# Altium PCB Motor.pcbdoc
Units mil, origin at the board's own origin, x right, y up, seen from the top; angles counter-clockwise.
Board outline 2316 x 2435.6 mil, 4 copper layers (Top Layer, SIG, GND, Bottom Layer), stack 62.5 mil thick; 70 components, 50 nets, 223 pads, 137 vias.
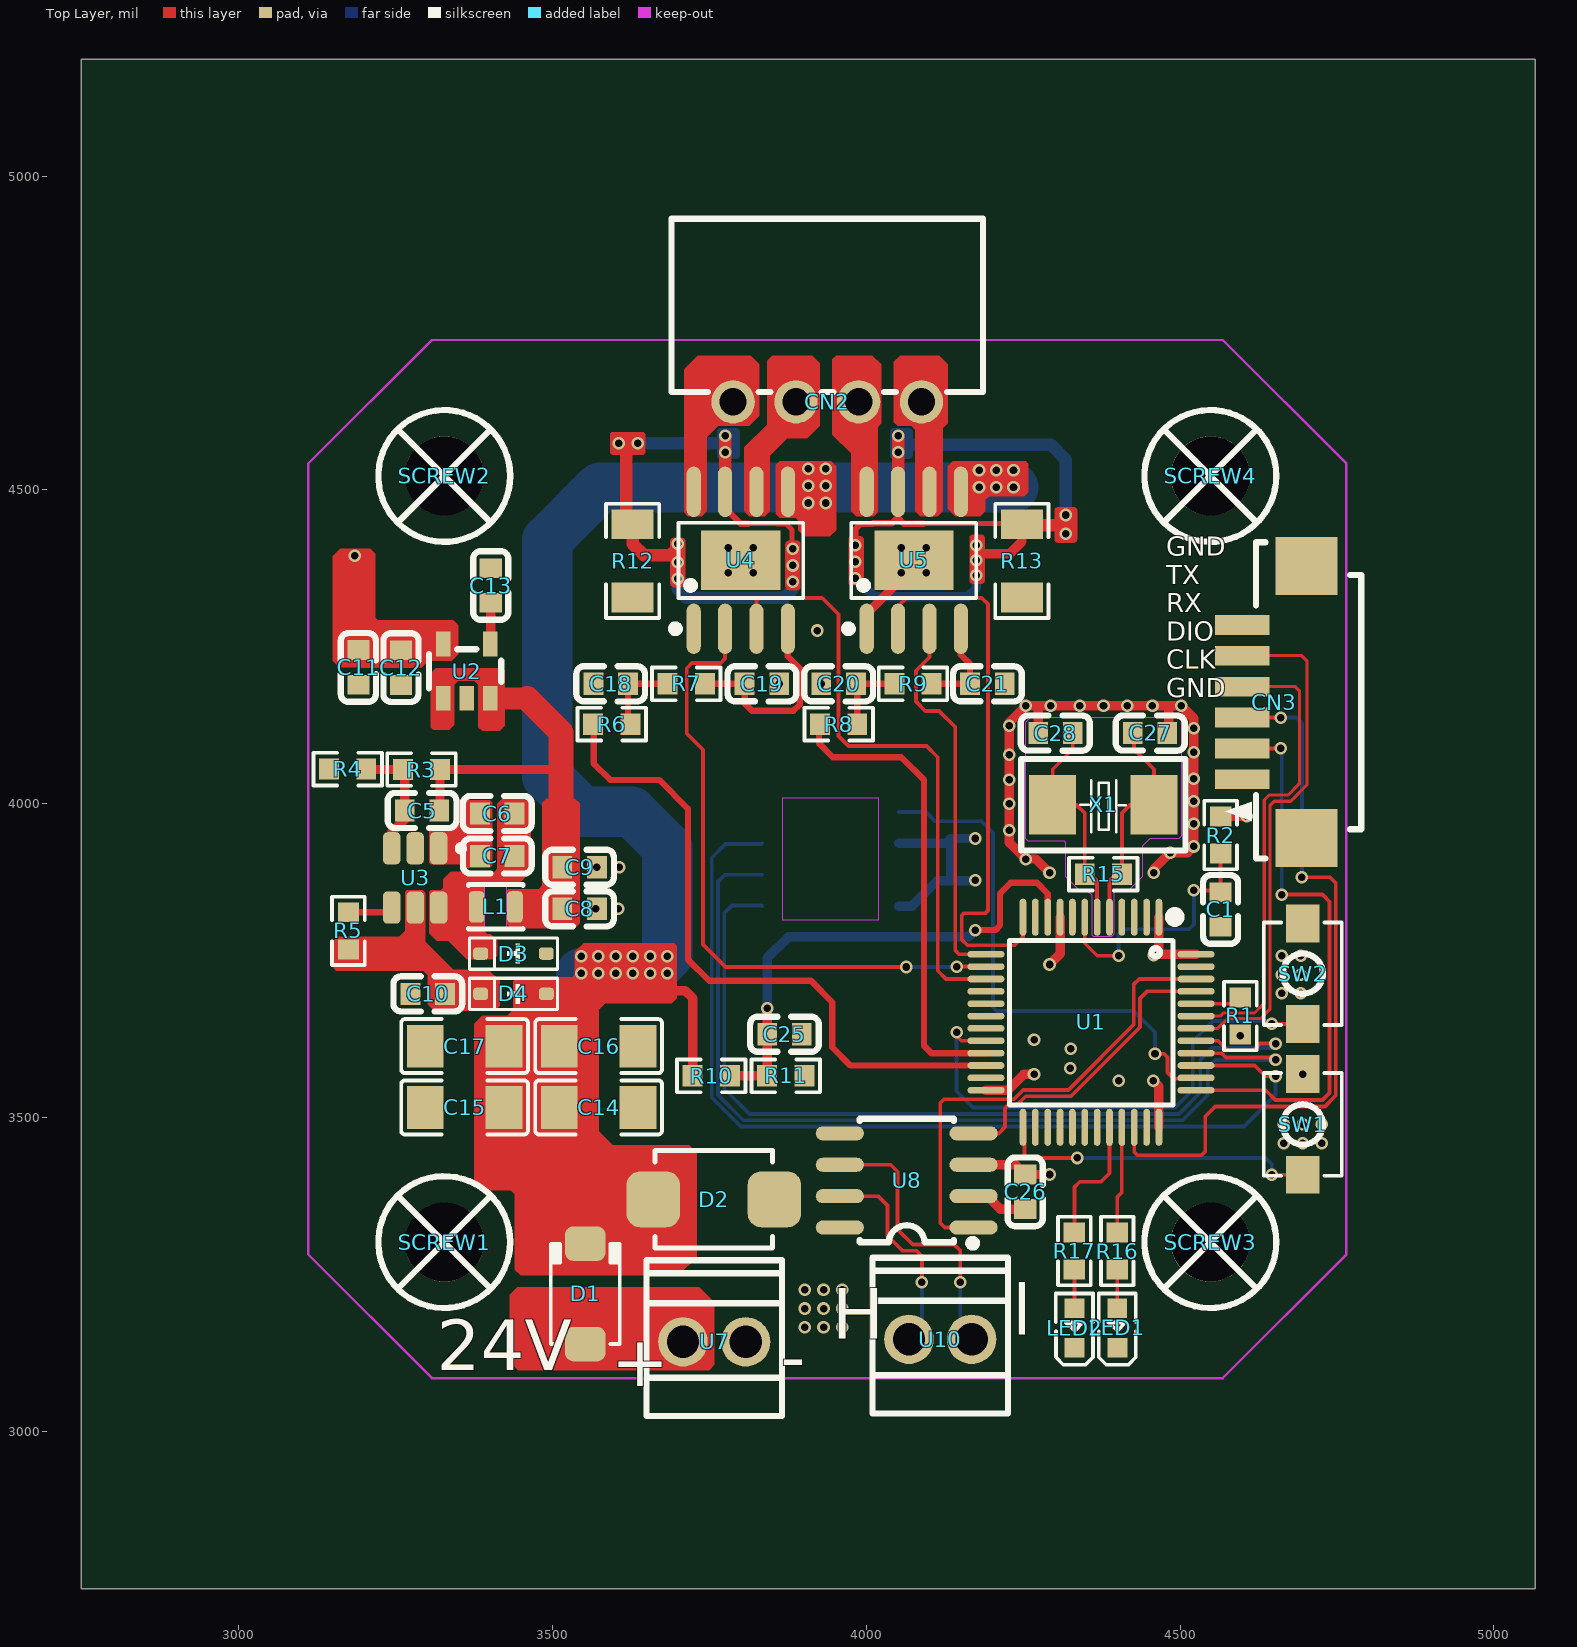
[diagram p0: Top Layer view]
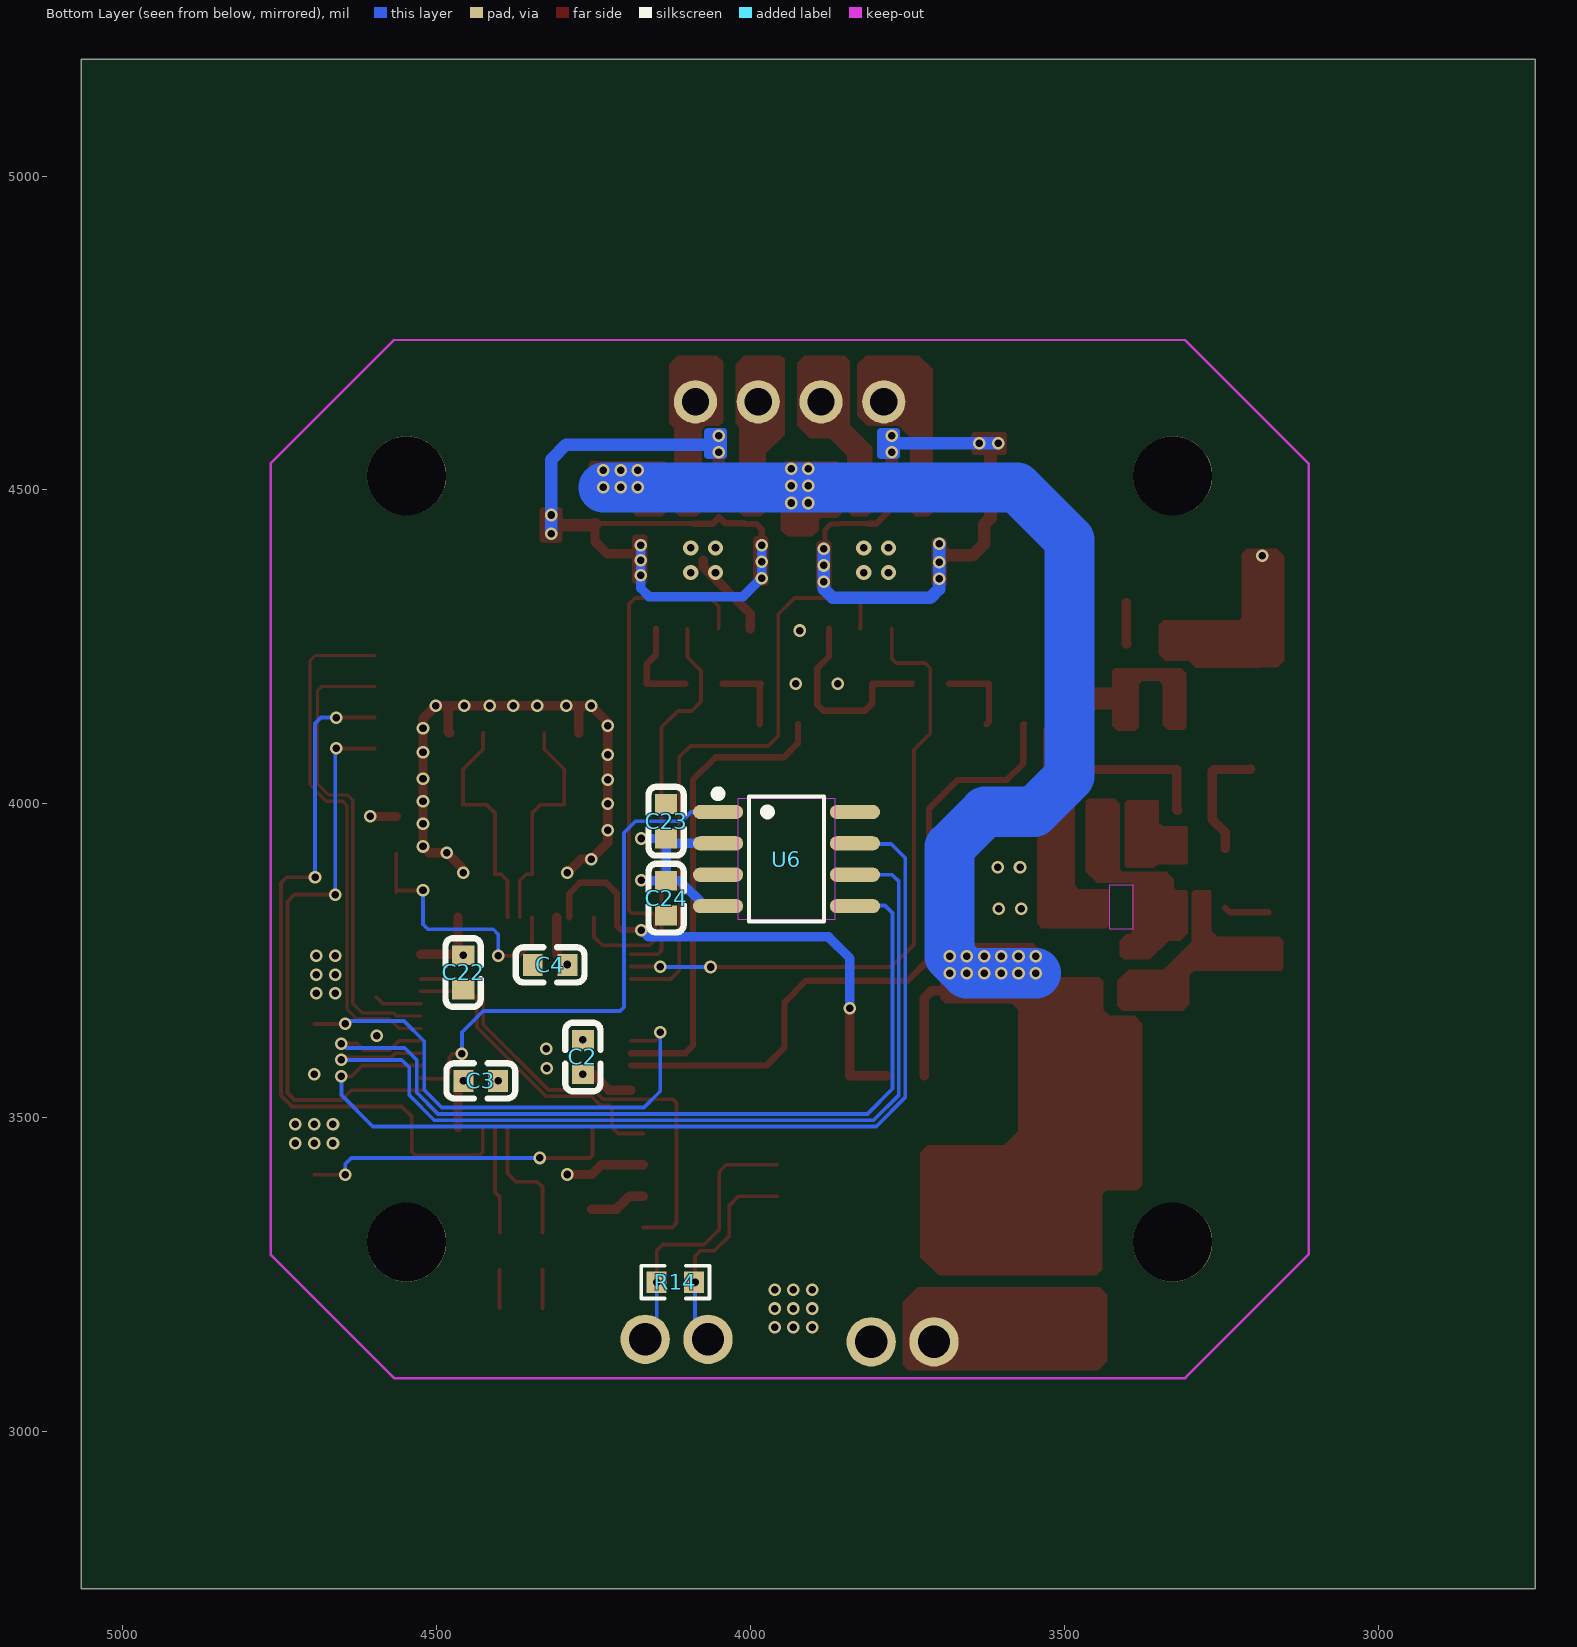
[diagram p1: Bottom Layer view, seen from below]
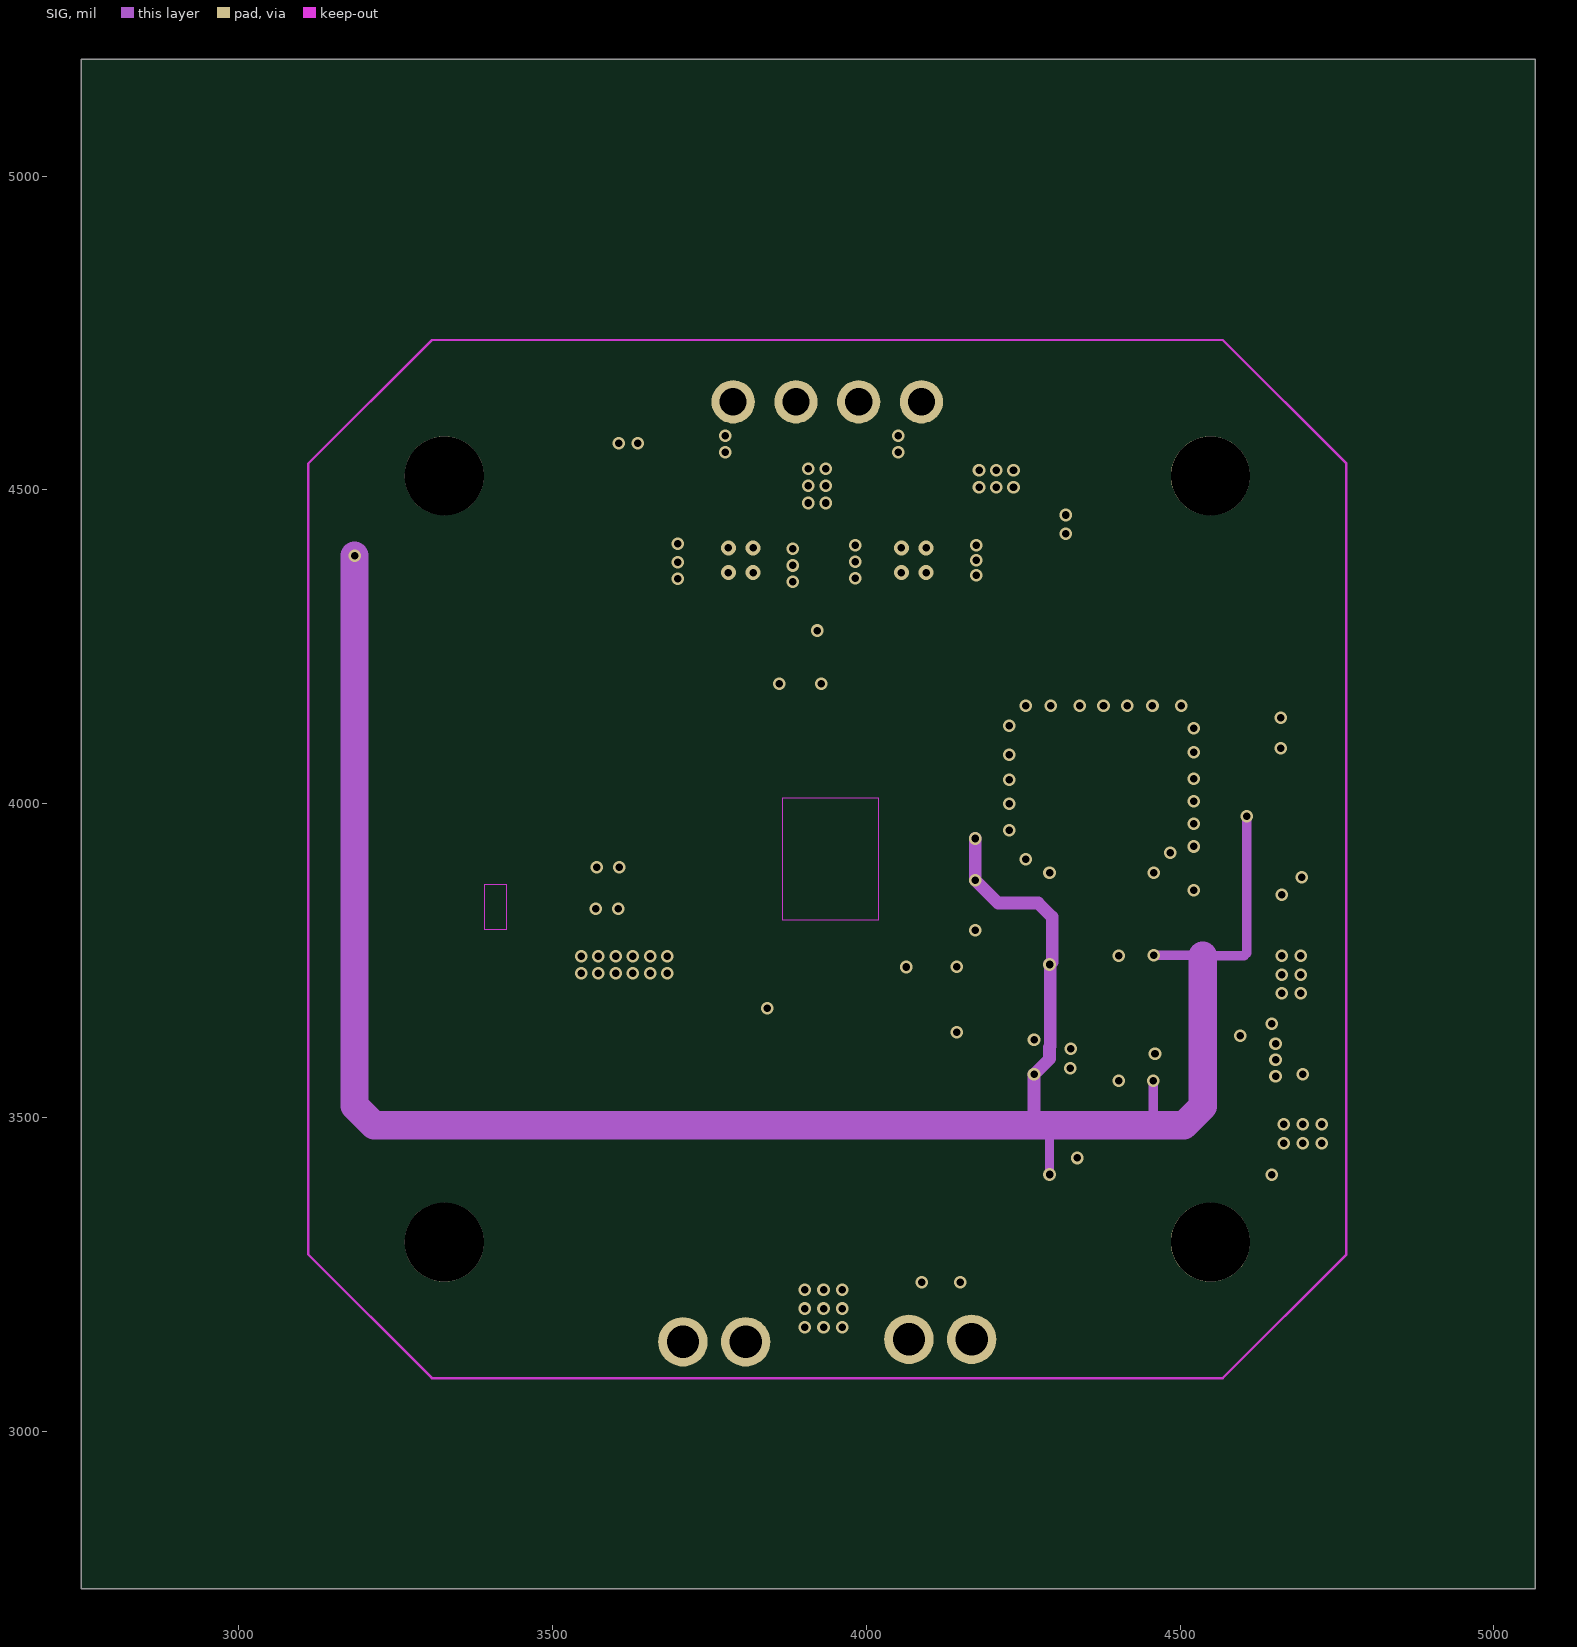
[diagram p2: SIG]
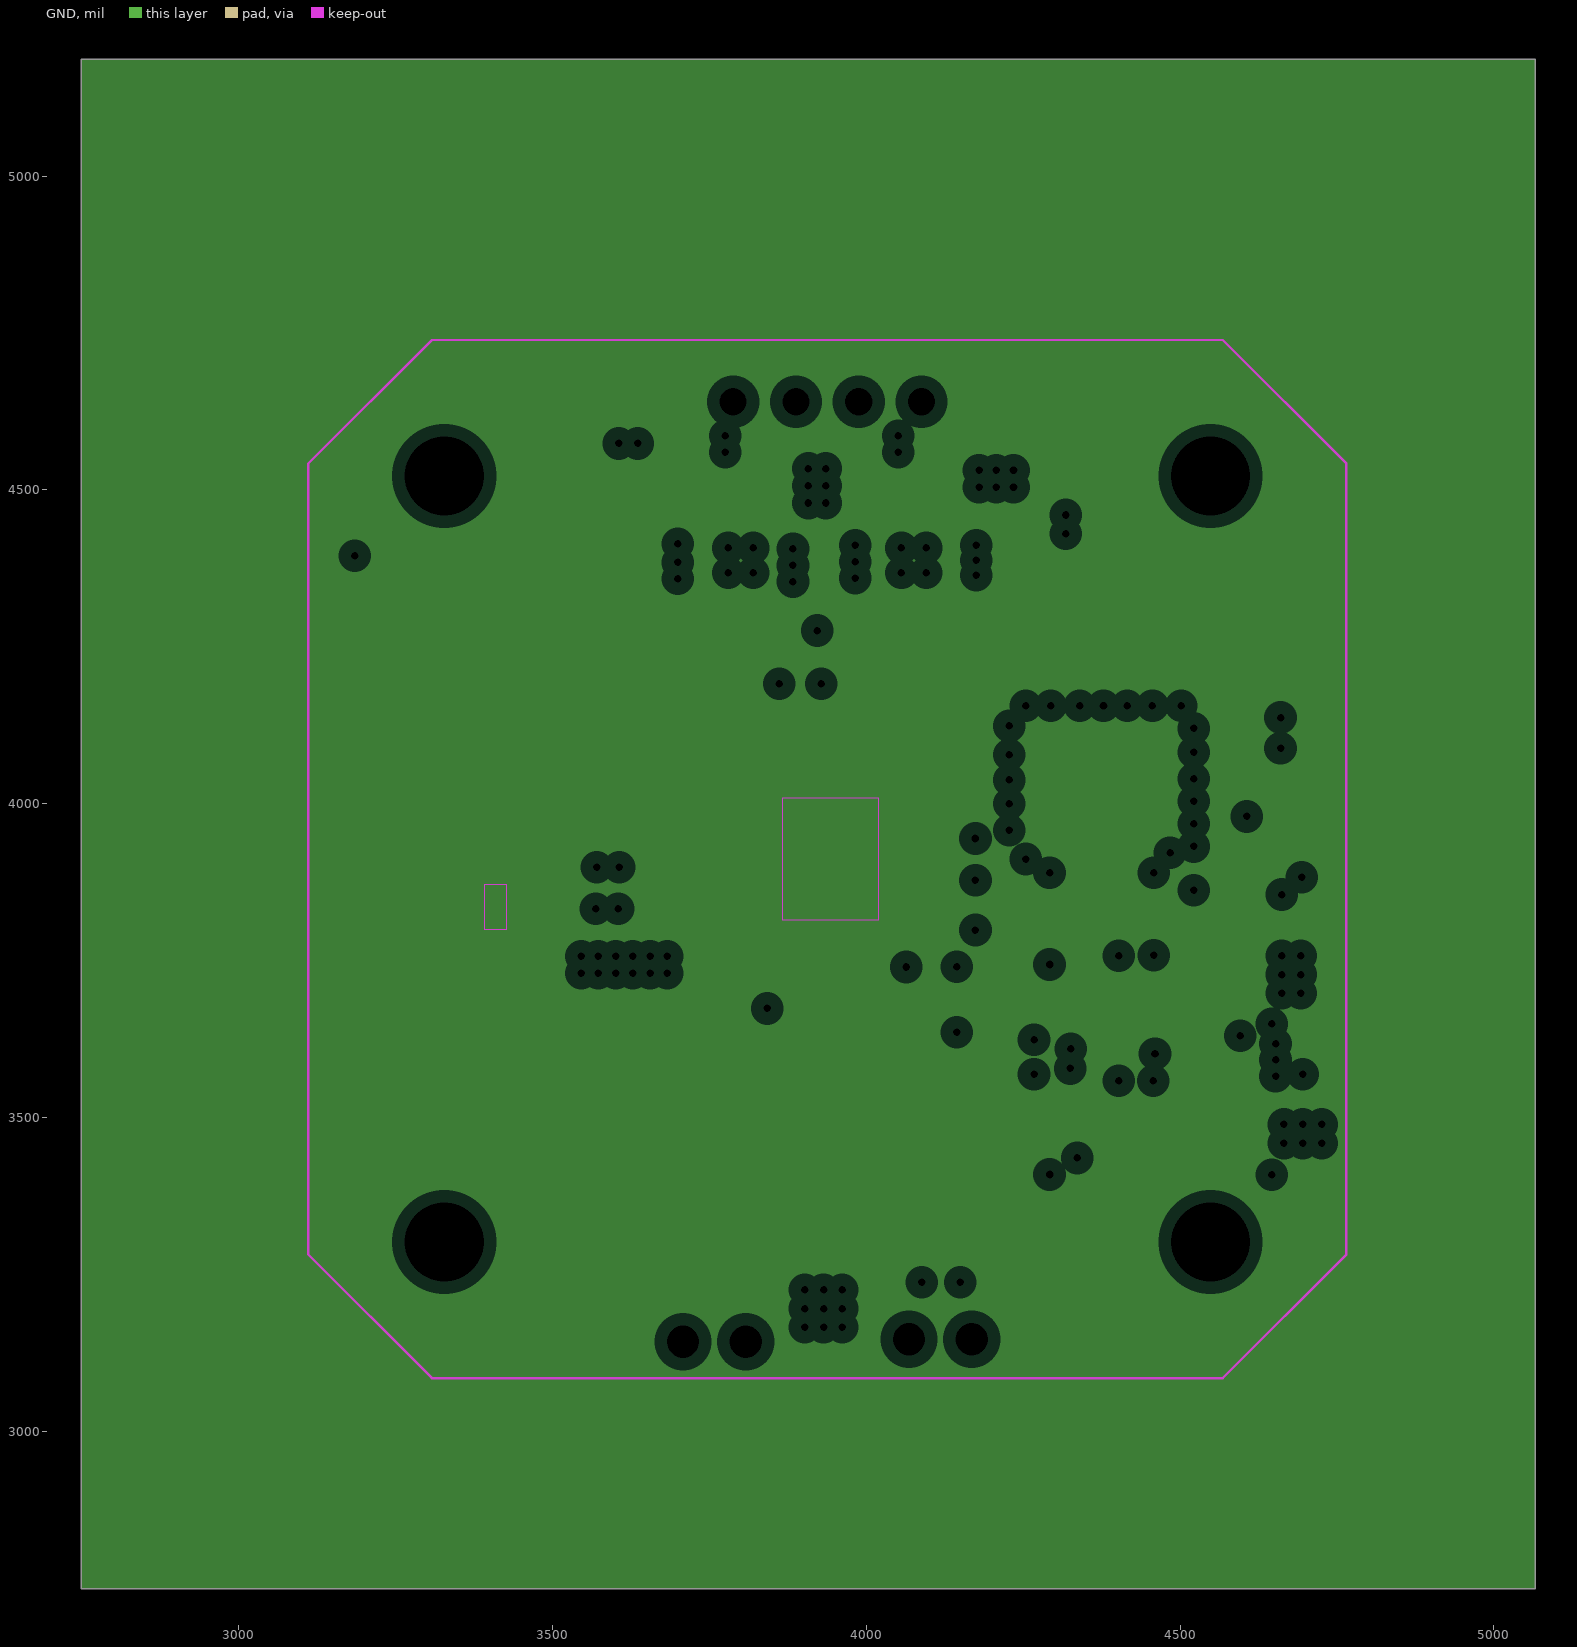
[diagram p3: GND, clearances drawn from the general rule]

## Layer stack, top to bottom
Top Layer: signal copper 1.4
Dielectric1: surface 8.3, 7628 RC49% 8.6mil, Dk 0
SIG: signal copper 0.6
Dielectric2: surface 41.9, 1.1mm H/HOZ Copper, Dk 0
GND: plane copper 0.6
Dielectric3: surface 8.3, 7628 RC49% 8.6mil, Dk 0
Bottom Layer: signal copper 1.4

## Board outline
5066,2750 2750,2750 2750,5185.6 5066,5185.6

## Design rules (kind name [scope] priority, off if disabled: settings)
BoardOutlineClearance copperThickness1oz [All] p0: genericclearance=10 ignorepadtopadclearanceinfootprint=FALSE except(0: Arc-SplitContinuation Track-SplitContinuation SMDPad-SplitContinuation THPad-SplitContinuation Via-SplitContinuation Fill-SplitContinuation Poly-SplitContinuation Region-SplitContinuation Text-SplitContinuation)
BoardOutlineClearance copperThickness2oz [All] p0: genericclearance=10 ignorepadtopadclearanceinfootprint=FALSE except(0: Arc-SplitContinuation Track-SplitContinuation SMDPad-SplitContinuation THPad-SplitContinuation Via-SplitContinuation Fill-SplitContinuation Poly-SplitContinuation Region-SplitContinuation Text-SplitContinuation)
BoardOutlineClearance otherClearance [All] p0: genericclearance=10 ignorepadtopadclearanceinfootprint=FALSE except(0: Arc-SplitContinuation Track-SplitContinuation SMDPad-SplitContinuation THPad-SplitContinuation Via-SplitContinuation Fill-SplitContinuation Poly-SplitContinuation Region-SplitContinuation Text-SplitContinuation)
Clearance copperThickness1oz [All] p1: gap=7 ignorepadtopadclearanceinfootprint=FALSE
Clearance copperThickness2oz [All] p1: gap=7 ignorepadtopadclearanceinfootprint=FALSE
Clearance otherClearance [All] p1: gap=7 ignorepadtopadclearanceinfootprint=FALSE
DiffPairsRouting differentialPair [All] p1: maxuncoupledlength=10 minlimit=6 maxlimit=Infinity mostfreqgap=6 toplayer_minwidth=5 toplayer_prefwidth=10 toplayer_maxwidth=100 bottomlayer_minwidth=5 bottomlayer_prefwidth=10 bottomlayer_maxwidth=100 midlayer1_minwidth=5 midlayer1_prefwidth=10 midlayer1_maxwidth=100
PasteMaskExpansion pasteMaskExpansion [All] p1: expansion=0
PlaneConnect innerPlane [All] p1: planeconnectstyle=Relief reliefexpansion=20 reliefentries=4 reliefconductorwidth=10 reliefairgap=10
PolygonConnect copperRegion [All] p1: connectstyle=Direct reliefentries=4 reliefconductorwidth=10 polygonreliefangle="90 Angle" airgapwidth=10
RoutingVias viaSize [All] p1: viastyle="Through Hole" holewidth=12.0078 minholewidth=12 maxholewidth=12.0078 width=12.0078 minwidth=12 maxwidth=12.0078
SolderMaskExpansion solderMaskExpansion [IsVia] p1: useseparateexpansions=TRUE expansion=-1000 expansionbottom=-1000
SolderMaskExpansion solderMaskExpansion [All] p2: useseparateexpansions=TRUE expansion=2 expansionbottom=2
Width copperThickness1oz [All] p1: maxlimit=100 minlimit=5 preferedwidth=6
Width copperThickness2oz [All] p1: maxlimit=100 minlimit=8 preferedwidth=10
Width PWR [All] p1: maxlimit=100 minlimit=10 preferedwidth=15

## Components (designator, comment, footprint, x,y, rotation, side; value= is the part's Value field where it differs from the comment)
C1 "100nF" C0603_2#1 4564.5,3831.7 r90 top
C2 "100nF" C0603_2#2 4267.3,3596.7 r270 bottom
C3 "100nF" C0603_2#3 4429.9,3558.6 r0 bottom
C4 "100nF" C0603_2#2 4319.5,3743.3 r180 bottom
C5 "100nF" C0603_2#3 3292.4,3989.3 r0 top
C6 "100nF" C0603_2#1 3412.4,3984.5 r0 top
C7 "100nF" C0603_2#1 3412.4,3916.9 r0 top
C8 "100nF" C0603_2#1 3543.4,3832.7 r180 top
C9 "100nF" C0603_2#1 3543.4,3898.9 r180 top
C10 "100nF" C0603_2#2 3301.6,3697.2 r0 top
C11 "100nF" C0603_2#2 3191.1,4217.2 r90 top
C12 "100nF" C0603_2#1 3258.9,4217 r90 top
C13 "100nF" C0603_2#2 3401.9,4347.7 r270 top
C14 "LMK316B7226ML-TR" C1206 3573.8,3516.3 r180 top
C15 "LMK316B7226ML-TR" C1206 3360.2,3516.3 r0 top
C16 "LMK316B7226ML-TR" C1206 3573.8,3614 r180 top
C17 "LMK316B7226ML-TR" C1206 3360.2,3614 r0 top
C18 "100nF" C0603_2#3 3592.9,4191.1 r0 top
C19 "100nF" C0603_2#3 3833.9,4191.1 r180 top
C20 "100nF" C0603_2#1 3956.1,4191.1 r0 top
C21 "100nF" C0603_2#2 4193,4191.1 r180 top
C22 "100nF" C0603_2#2 4458,3731.3 r90 bottom
C23 "100nF" C0603_2#1 4134.8,3972.2 r270 bottom
C24 "100nF" C0603_2#1 4134.8,3849.8 r90 bottom
C25 "100nF" C0603_2#1 3869.7,3632.9 r180 top
C26 "100nF" C0603_2#3 4253.2,3381.9 r90 top
C27 "22pF" C0603_1#1 4452,4112.8 r180 top
C28 "22pF" C0603_1#2 4301.4,4112.6 r0 top
CN2 "XH-4AW" CONN-TH_XH-4AW 3938,4640.3 r180 top
CN3 "1.25-6PWT" CONN-SMD_1.25-6PWT-C2763634 4650,4162 r90 top
D1 "=value" DO-214AC 3552.5,3219.3 r90 top
D2 "SMBJ28CA" SMBJ-CA_MFG 3757.3,3369.9 r0 top
D3 "二极管-5819W" SOD-323 3438,3761.4 r180 top
D4 "二极管-5819W" SOD-323 3438.1,3697.2 r180 top
L1 "6.8uH" IND-201612 3409.9,3835.7 r0 top
LED1 "" LED_0603 4399.8,3167.1 r90 top
LED2 "" LED_0603 4331.6,3167.1 r90 top
R1 "10K" R0603_2#1 4596,3662 r270 top
R2 "10K" R0603_2#2 4564.5,3950.1 r90 top
R3 "10K" R0603_2#3 3291.5,4054.6 r0 top
R4 "10K" R0603_2#3 3174,4055.3 r0 top
R5 "10K" R0603_2#3 3175.2,3797.6 r90 top
R6 "10K" R0603_2#2 3594.7,4126.8 r0 top
R7 "10K" R0603_2#1 3713.4,4191.1 r0 top
R8 "10K" R0603_2#3 3956.1,4126.8 r0 top
R9 "10K" R0603_2#2 4074.5,4191.1 r0 top
R10 "10K" R0603_2#2 3753.3,3566.6 r180 top
R11 "10K" R0603_2#3 3871.7,3566.6 r180 top
R12 "10K" R1206 3628,4387 r270 top
R13 "10K" R1206 4248,4387 r270 top
R14 "10K" R0603_2#1 4120,3238 r180 bottom
R15 "10K" R0603_1 4377.7,3887.9 r180 top
R16 "10K" R0603_2#3 4399.8,3287.6 r90 top
R17 "10K" R0603_2#3 4331.6,3287.6 r90 top
SCREW1 "" M3螺丝 3327.8,3301.8 r0 top locked
SCREW2 "" M3螺丝 3327.8,4522.2 r0 top locked
SCREW3 "" M3螺丝 4548.2,3301.8 r0 top locked
SCREW4 "" M3螺丝 4548.2,4522.2 r0 top locked
SW1 "" Key_SMD_3x4x2_1#1 4695.4,3489.2 r90 top
SW2 "" Key_SMD_3x4x2_1#2 4695.4,3729.4 r90 top
U1 "STM32F103CBT6" LQFP-48_L7.0-W7.0-P0.50-LS9.0-BL 4358,3652 r180 top
U2 "LP2992IM5-3.3" SOT-23-5_L2.9-W1.6-P0.95-LS2.8-BL 3363.7,4211.2 r0 top
U3 "ME3116" SOT23-6 3281.6,3881.9 r270 top
U4 "TB67H450FNG,EL" HSOP-8_L5.0-W4.0-P1.27-LS6.2-BL-EP 3800.2,4387.9 r0 top
U5 "TB67H450FNG,EL" HSOP-8_L5.0-W4.0-P1.27-LS6.2-BL-EP 4075.8,4387.9 r0 top
U6 "MT6816CT-ACD" SOP-8_L5.0-W4.0-P1.27-LS6.0-BL 3943,3912 r270 bottom
U7 "KF128-2.54-2P" CONN-TH_P2.54_KF128-2.54-2P 3758,3143 r180 top
U8 "SN65HVD232DR" SOIC-8_L5.0-W4.0-P1.27-LS6.0-BL 4064.5,3400 r90 top
U10 "KF128-2.54-2P" CONN-TH_P2.54_KF128-2.54-2P 4118,3147 r180 top
X1 "12MHz" OSC-SMD_L5.0-W3.2 4377.7,3998.3 r0 top

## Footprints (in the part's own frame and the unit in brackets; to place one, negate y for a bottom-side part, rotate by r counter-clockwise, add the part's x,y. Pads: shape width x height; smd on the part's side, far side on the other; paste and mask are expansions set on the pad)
C0603_1#1 [mil]
  rect 31.5x35.4 smd paste+0 mask+2: 1(-27.6,0) 2(27.5,0)
  silkscreen extent -55,-28 55,28
C0603_1#2 [mil]
  rect 31.5x35.4 smd paste+0 mask+2: 1(-27.5,0) 2(27.6,0)
  silkscreen extent -55,-28 55,28
C0603_2#1 [mil]
  rect 31.5x35.4 smd: 1(-27.6,0) 2(27.5,0)
  silkscreen extent -55,-28 55,28
C0603_2#2 [mil]
  rect 31.5x35.4 smd: 1(-27.6,0) 2(27.6,0)
  silkscreen extent -55,-28 55,28
C0603_2#3 [mil]
  rect 31.5x35.4 smd: 1(-27.5,0) 2(27.6,0)
  silkscreen extent -55,-28 55,28
C1206 [mil]
  rect 58.5x68 smd paste-3937 mask+2: 1(-62.7,0) 2(62.7,0)
  silkscreen extent -101,-43 101,43
CONN-SMD_1.25-6PWT-C2763634 [mil]
  rect 31.5x86.6 smd paste+0 mask+2: 1(-123,51.2) 2(-73.8,51.2) 3(-24.6,51.2) 4(24.6,51.2) 5(73.8,51.2) 6(123,51.2)
  rect 92.5x98.4 smd paste+0 mask+2: 7(216.7,-51.2) 8(-216.7,-51.2)
  silkscreen extent -249,-138 255,79
CONN-TH_P2.54_KF128-2.54-2P [mil]
  round 78.7 hole 51.2: 1(-50,0) 2(50,0)
  silkscreen extent -108,-130 108,118
CONN-TH_XH-4AW [mil]
  round 68.9 hole 43.3 paste+0 mask+2: 1(-150,0) 2(-50,0) 3(50,0) 4(150,0)
  silkscreen extent -248,-291 248,-16
DO-214AC [mil]
  rrect50% 55x65 smd: 1(-80,0) 2(80,0)
  silkscreen extent -80,-55 80,55
HSOP-8_L5.0-W4.0-P1.27-LS6.2-BL-EP [mil]
  oval 22.6x80.2 smd: 1(-75,-109.1) 2(-25,-109.1) 3(25,-109.1) 4(75,-109.1) 5(75,109) 6(25,109) 7(-25,109) 8(-75,109)
  rect 126x94.5 smd: 9(0,0)
  silkscreen extent -110,-115 100,60
IND-201612 [mil]
  rrect50% 25x50 smd paste+0 mask+0: 1(-30.5,0) 2(30.5,0)
  silkscreen extent -43,-35 43,35
Key_SMD_3x4x2_1#1 [mil]
  rect 60.2x53.5 smd paste+0 mask+2: 1(-80.1,0) 2(80.2,0)
  silkscreen extent -82,-62 82,62
Key_SMD_3x4x2_1#2 [mil]
  rect 60.2x53.5 smd paste+0 mask+2: 1(-80.1,0) 2(80.1,0)
  silkscreen extent -82,-62 82,62
LED_0603 [mil]
  rect 31.5x31.5 smd paste+0 mask+2: 1(-33.5,-0.4) 2(29.5,-0.2)
  silkscreen extent -61,-30 53,30
LQFP-48_L7.0-W7.0-P0.50-LS9.0-BL [mil]
  oval 10.6x59.1 smd paste+0 mask+2: 1(-108.3,-167.3) 2(-88.6,-167.3) 3(-68.9,-167.3) 4(-49.2,-167.3) 5(-29.5,-167.3) 6(-9.8,-167.3) 7(9.8,-167.3) 8(29.5,-167.3) 9(49.2,-167.3) 10(68.9,-167.3) 11(88.6,-167.3) 12(108.3,-167.3) 25(108.3,167.3) 26(88.6,167.3) 27(68.9,167.3) 28(49.2,167.3) 29(29.5,167.3) 30(9.8,167.3) 31(-9.8,167.3) 32(-29.5,167.3) 33(-49.2,167.3) 34(-68.9,167.3) 35(-88.6,167.3) 36(-108.3,167.3)
  oval 59.1x10.6 smd paste+0 mask+2: 13(167.3,-108.3) 14(167.3,-88.6) 15(167.3,-68.9) 16(167.3,-49.2) 17(167.3,-29.5) 18(167.3,-9.8) 19(167.3,9.8) 20(167.3,29.5) 21(167.3,49.2) 22(167.3,68.9) 23(167.3,88.6) 24(167.3,108.3) 37(-167.3,108.3) 38(-167.3,88.6) 39(-167.3,68.9) 40(-167.3,49.2) 41(-167.3,29.5) 42(-167.3,9.8) 43(-167.3,-9.8) 44(-167.3,-29.5) 45(-167.3,-49.2) 46(-167.3,-68.9) 47(-167.3,-88.6) 48(-167.3,-108.3)
  silkscreen extent -141,-176 130,132
M3螺丝 [mil]
  round 126 hole 126 paste+0 mask+4: 1(0,0)
  silkscreen extent -105,-105 105,105
OSC-SMD_L5.0-W3.2 [mil]
  rect 74.8x94.5 smd: 1(-80.7,0) 2(80.7,0)
  silkscreen extent -131,-73 131,73
R0603_1 [mil]
  rect 31.8x34 smd paste-3937 mask+2: 1(-29.7,0) 2(29.6,0)
  silkscreen extent -55,-26 54,26
R0603_2#1 [mil]
  rect 31.8x34 smd paste-3937 mask+2: 1(-29.7,0) 2(29.7,0)
  silkscreen extent -55,-26 55,26
R0603_2#2 [mil]
  rect 31.8x34 smd paste-3937 mask+2: 1(-29.6,0) 2(29.7,0)
  silkscreen extent -54,-26 55,26
R0603_2#3 [mil]
  rect 31.8x34 smd paste-3937 mask+2: 1(-29.7,0) 2(29.6,0)
  silkscreen extent -55,-26 54,26
R1206 [mil]
  rect 47.5x67 smd paste-3937 mask+2: 1(-58.2,0) 2(58.2,0)
  silkscreen extent -91,-43 91,43
SMBJ-CA_MFG [mil]
  rrect50% 85x89 smd paste+0 mask+0: 1(-96.5,0) 2(96.4,0)
  silkscreen extent -94,-78 94,78
SOD-323 [mil]
  rrect50% 23.6x19.7 smd: 1(-52.4,0) 2(52.3,0)
  silkscreen extent -70,-25 70,25
SOIC-8_L5.0-W4.0-P1.27-LS6.0-BL [mil]
  oval 22.4x76.8 smd: 1(-75,-106.5) 2(-25,-106.5) 3(25,-106.5) 4(75,-106.5) 5(75,106.5) 6(25,106.5) 7(-25,106.5) 8(-75,106.5)
  silkscreen extent -106,-111 98,75
SOP-8_L5.0-W4.0-P1.27-LS6.0-BL [mil]
  oval 22.6x80.1 smd: 1(-75,-109) 2(-25,-109) 3(25,-109) 4(75,-109) 5(75,109) 6(25,109) 7(-25,109) 8(-75,109)
  silkscreen extent -110,-115 100,60
SOT23-6 [mil]
  rrect50% 51.2x27.6 smd: 1(-47.2,37.4) 2(-47.2,0) 3(-47.2,-37.4) 4(47.3,-37.4) 5(47.3,0) 6(47.3,37.4)
  silkscreen extent -52,68 -42,78
SOT-23-5_L2.9-W1.6-P0.95-LS2.8-BL [mil]
  rect 23.6x39.4 smd paste+0 mask+2: 1(-37.4,-43.3) 2(0,-43.3) 3(37.4,-43.3) 4(37.4,43.3) 5(-37.4,43.3)
  silkscreen extent -60,-28 55,35

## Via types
v1: diameter 20, hole 12, Top Layer to Bottom Layer, 129 vias
v2: diameter 24, hole 12, Top Layer to Bottom Layer, 8 vias

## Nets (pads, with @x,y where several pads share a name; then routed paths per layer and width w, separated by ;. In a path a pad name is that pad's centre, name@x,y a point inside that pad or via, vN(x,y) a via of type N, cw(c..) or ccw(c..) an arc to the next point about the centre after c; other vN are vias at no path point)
$1N21: R1.1 U1.44 | length 75
  Top Layer w6: U1.44 4585.9,3681.5 R1.1
$1N67: C6.2 C7.2 D3.2 L1.1 U3.6
$1N69: C5.1 R3.1 R4.2 U3.3 | length 193.8
  Top Layer w15: R4.2 3204.4,4054.6 R3.1 3264.9,4051.5 C5.1 3264.9,3974.9 3244.2,3954.2 U3.3
$1N70: C6.1 C7.1 U3.1
$1N73: R5.2 U3.4 | length 72.1
  Top Layer w10: R5.2 3236.8,3827.2 U3.4
$1N90: C10.2 D4.2 R5.1 U3.5
$1N94: C13.2 U2.4 | length 66
  Top Layer w15: U2.4 3401.9,4255.2 C13.2
$1N128: C18.2 R6.2 R7.1 | length 129.1
  Top Layer w10: R6.2 3620.5,4130.8 C18.2 R7.1
$1N135: C20.2 R8.2 R9.1 | length 126.5
  Top Layer w10: R8.2 3985.7,4189 C20.2 R9.1
$1N196: LED1.2 R16.1 | length 61.4
  Top Layer w6: R16.1 4400,3257.7 LED1.2
$1N198: LED2.2 R17.1 | length 61.4
  Top Layer w6: R17.1 4331.6,3196.8 LED2.2
$1N214: R12.1 U4.7 | length 997
  Top Layer w8: 3812,4446.1 3857.8,4446.1 3857.9,4446 3872,4446 3882,4436 v1@3882,4400
  Top Layer w10: U4.7 3775.2,4470.9 3800,4446.1 3812,4446.1
  Top Layer w20: 3618,4568 3618,4455.2 R12.1 3628,4414 3646,4396 3688,4396 3692,4400 ; U4.7 v1(3775.2,4560) v1@3775.2,4584
  Bottom Layer w20: v1(3606,4574) v1(3635.8,4574) 3770,4574 ; v1(3699.9,4414) v1(3699.9,4384.4) v1(3699.9,4358.6) 3699.9,4342 3714,4327.9 3869.2,4327.9 3883.3,4342 v1(3883.3,4354) v1(3883.3,4379.6) v1(3883.3,4406.3)
  other v1: 3775.2,4586
$1N216: R13.1 U5.7 | length 1260.2
  Top Layer w8: 4091.2,4446.1 R13.1@4247.1,4446.1
  Top Layer w10: v1(3982.6,4412) 3982.6,4437.4 3990.9,4445.8 4010,4445.8 4011.2,4447 4041,4447 U5.7@4050.8,4456.8 ; 4050.8,4455.3 4060,4446.1 4091.2,4446.1
  Top Layer w15: 4186,4398 4228,4398 4248,4418 R13.1
  Top Layer w20: U5.7 v1(4050.8,4560) v1(4050.8,4586) ; R13.1 4249.2,4444 4308,4444
  Bottom Layer w15: v1(3982.6,4412) v1(3982.6,4385.3) v1(3982.6,4359.6) 4012.2,4330 4162,4330 4175.2,4343.2 v1(4175.2,4363.9) v1(4175.2,4387.9) v1(4175.2,4411.9)
  Bottom Layer w20: 4066,4572 4294,4572 4318,4548 v1(4318,4460) v1(4318,4430)
+5V: C5.2 C8.2 C9.2 L1.2 R3.2 U2.1 U2.3 | length 515.7
  Top Layer w15: C5.2 3321.1,3990.4 R3.2 3503.4,4054.6
  Top Layer w35: U2.3@3401.5,4167.9 3460.1,4167.9
  Top Layer w40: 3460.1,4167.9 3514,4114 3514,3984 3512,3982
BUTTON_1: SW1.1 U1.25 | length 511.8
  Top Layer w6: U1.25 4252,3482.4 4252,3440 4256.2,3435.8 v1(4336,3435.8) ; v1(4646,3409.1) SW1.1
  Bottom Layer w6: v1(4336,3435.8) 4636.2,3435.8 4646,3426 v1(4646,3409.1)
BUTTON_2: SW2.1 U1.20 | length 816.7
  Top Layer w6: v1(4144,3636) 4144,3630 4151.5,3622.5 U1.20 ; v1(4646,3649.3) SW2.1
  Bottom Layer w6: v1(4144,3636) 4144,3542 4170,3516 4492,3516 4520,3544 4520,3621.8 4552.2,3654 4641.3,3654 v1(4646,3649.3)
CAN_H: R14.2 U8.7 U10.2 | length 339.3
  Top Layer w6: U8.7 4019,3375 4034,3360 4034,3312 4058,3288 4080,3288 4088.7,3279.3 v1(4088.7,3238)
  Bottom Layer w6: U10.2 4088.7,3167.7 v1(4088.7,3238)
CAN_L: R14.1 U8.6 U10.1 | length 451.1
  Top Layer w6: U8.6 4039,3425 4050,3414 4050,3322 4074,3298 4140,3298 4149.7,3288.3 v1(4149.7,3238)
  Bottom Layer w6: v1(4149.7,3238) 4149.7,3165.3 U10.1
CAN_RX: U1.45 U8.4 | length 492.6
  Top Layer w6: U8.4 4211,3475 4221,3485 4221,3515 4225.2,3519.2 4239.4,3519.2 4254.1,3534 4326.1,3534 4436,3643.9 4436,3690 4447.2,3701.2 U1.45
CAN_TX: U1.46 U8.1 | length 773.8
  Top Layer w6: U8.1 4125,3325 4118,3332 4118,3523.2 4124,3529.2 4235.2,3529.2 4250,3544 4322,3544 4426,3648 4426,3712 4434.9,3720.9 U1.46
GND: C1.1 C2.1 C3.1 C4.1 C8.1 C9.1 C10.1 C11.1 C12.1 C13.1 C14.1 C15.1 C16.1 C17.1 C18.1 C19.1 C20.1 C21.1 C22.1 C23.1 C24.1 C25.1 C26.1 C27.1 C28.1 CN3.1 CN3.6 CN3.7 CN3.8 D2.2 D3.1 LED1.1 LED2.1 R1.2 R4.1 R11.1 R12.2 R13.2 SCREW1.1 SCREW2.1 SCREW3.1 SCREW4.1 SW1.2 SW2.2 U1.8 U1.23 U1.35 U1.47 U2.2 U3.2 U4.1 U4.9 U5.1 U5.9 U6.8 U7.1 U8.2 | length 1196.4
  Top Layer w15: U5.1 4000.8,4302.8 4075.8,4377.8 U5.9 ; U8.2 4193,3375 4213.6,3354.4 C26.1 ; C28.1 4273.9,4155.4 4273.3,4156 ; v1(4292,3890) 4270,3912 v1(4254,3912) 4228,3938 v1(4228,3958) v1(4228,4000) v1(4228,4038) v1(4228,4078) 4228,4130 v1(4254,4156) 4273.3,4156 ; v1(4458,3890) 4458,3896 v1(4484,3922) 4512,3922 v1(4522,3932) v1(4522,3968) v1(4522,4004) v1(4522,4040) v1(4522,4082) v1(4522,4120) 4522,4136 v1(4502,4156) 4481.6,4156 ; C27.1 4481.6,4114.8 4481.6,4156 ; 4273.3,4156 v1(4294,4156) v1(4340,4156) v1(4378,4156) v1(4416,4156) v1(4456,4156) 4481.6,4156
  other v1: 3902,3166 3932,3166 3962,3166 3902,3196 3932,3196 3962,3196 3902,3226 3932,3226 3962,3226 4665.4,3459.2 4695.4,3459.2 4725.4,3459.2 4665.4,3489.2 4695.4,3489.2 4725.4,3489.2 4402.4,3558.6 4695.4,3569.4 4325.1,3578.4 4326,3610 4267.3,3624.3 4596,3630.7 4662,3698 4692,3698 4662,3728 4692,3728 4662,3758 4692,3758 3569,3832.7 3604.8,3832.7 3571,3898.9 3606.8,3898.9 4228,4124 3861.4,4191.1 3928.5,4191.1 3922,4276
  other v2: 3780.5,4368.2 3819.9,4368.2 4056.1,4368.2 4095.5,4368.2 3780.5,4407.5 3819.9,4407.5 4056.1,4407.5 4095.5,4407.5
IN_AM: U1.14 U4.2 | length 1031.7
  Top Layer w6: U4.2 3775.2,4231.2 3768.2,4224.2 3722.2,4224.2 3714,4216 3714,4112 3740,4086 3740,3776 3776,3740 v1(4064,3740) ; v1(4144,3740.6) U1.14
  Bottom Layer w6: v1(4064,3740) 4143.4,3740 v1(4144,3740.6)
IN_AP: U1.15 U4.3 | length 976.2
  Top Layer w6: U4.3 3825.2,4323.2 3830,4328 3930,4328 3956,4302 3956,4108 3972,4092 4096,4092 4114,4074 4114,3734 4127.1,3720.9 U1.15
IN_BM: U1.12 U5.2 | length 898.6
  Top Layer w6: U5.2 4050.8,4314.8 4064,4328 4184,4328 4194,4318 4194,3830 4189.8,3825.8 4156,3825.8 4152,3821.8 4152,3784 4161.4,3774.6 4236.6,3774.6 4249.7,3787.7 U1.12
IN_BP: U1.13 U5.3 | length 611.4
  Top Layer w6: U5.3 4100.8,4233.3 4079.3,4211.8 4079.3,4162.7 4094,4148 4116,4148 4142,4122 4142,3766.3 4148,3760.3 U1.13
IN_PWM_A: R6.1 U1.22 | length 1069.8
  Top Layer w10: R6.1 3566,4125.9 3566,4064 3592,4038 3670,4038 3716,3992 3716,3752 3750,3718 3912,3718 3946,3684 3946,3612 3974.9,3583.1 U1.22
IN_PWM_B: R8.1 U1.21 | length 748.8
  Top Layer w10: R8.1@3924.8,4126.8 3924.8,4096.2 3946.9,4074 4056,4074 4092,4038 4092,3614.8 4104,3602.8 U1.21
LED1: R16.2 U1.33 | length 170.6
  Top Layer w6: R16.2 4399.8,3373.8 4407.2,3381.2 U1.33
LED2: R17.2 U1.32 | length 210.6
  Top Layer w6: R17.2 4331.6,3389.6 4340,3398 4374,3398 4387.5,3411.5 U1.32
MT6816_CS: U1.38 U6.1 | length 846.7
  Top Layer w6: v1(4460,3602) 4474,3602 4479.8,3596.2 4479.8,3572.2 4490,3562 4523.9,3562 U1.38
  Bottom Layer w6: U6.1 4095,3987 4110,3972 4184,3972 4202,3954 4202,3676 4208,3670 4426,3670 4460,3636 v1(4460,3602)
NRST: C1.2 R2.1 U1.7 | length 423.1
  Top Layer w6: U1.7 4348.2,3777.8 4368,3758 v1(4402,3758) ; v1(4522,3862) 4561.7,3862 C1.2 R2.1
  Bottom Layer w6: v1(4402,3758) 4402,3792 4410,3800 4514,3800 4522,3808 v1(4522,3862)
OSC_IN: C27.2 R15.1 U1.5 X1.2 | length 363.7
  Top Layer w6: U1.5 4387.5,3877.5 4397.9,3887.9 R15.1 4407.4,3985.4 4420.3,3998.3 X1.2 4458.4,4055 4426.5,4087 C27.2@4426.5,4112.6
OSC_OUT: C28.2 R15.2 U1.6 X1.1 | length 363.7
  Top Layer w6: C28.2 4329,4087 4297,4055 X1.1 4335.1,3998.3 4348.1,3985.4 R15.2 4357.5,3887.9 4367.8,3877.5 U1.6
OUT_A+: CN2.3 U4.6
OUT_A-: CN2.4 U4.8
OUT_B+: CN2.1 U5.6
OUT_B-: CN2.2 U5.8
POWER_U: C25.2 R10.1 R11.2 U1.10 | length 817.9
  Top Layer w10: v1(4174,3798.9) 4205.9,3798.9 4213,3806 4213,3857 4230,3874 4272,3874 4289.1,3856.9 U1.10
  Top Layer w15: R10.1 R11.2 3842.1,3632.8 C25.2 v1(3842.2,3674)
  Bottom Layer w15: v1(3842.2,3674) 3842.2,3754.2 3876,3788 4163.1,3788 v1(4174,3798.9)
SPI1_MISO: U1.40 U6.6 | length 1515.7
  Top Layer w6: U1.40 4565.8,3602.8 4572.6,3596 4648,3596 v1(4652,3592)
  Bottom Layer w6: U6.6 3775,3887 3764,3876 3764,3536.1 3804.2,3496 4504,3496 4544,3536 4544,3580 4556,3592 v1(4652,3592)
SPI1_MOSI: U1.41 U6.5 | length 1454.1
  Top Layer w6: U1.41 4560.3,3622.5 4575.3,3607.5 4616.7,3607.5 4627.2,3618 v1(4652,3618)
  Bottom Layer w6: U6.5 3833,3838 3786,3838 3774,3826 3774,3546 3814,3506 4498,3506 4532,3540 4532,3592 4551,3611 4645,3611 v1(4652,3618)
SPI1_SCK: U1.39 U6.7 | length 1573.1
  Top Layer w6: U1.39 4618.9,3583.1 4636,3566 v1(4652,3566)
  Bottom Layer w6: U6.7 3833,3936 3776,3936 3754,3914 3754,3532 3800,3486 4602,3486 4652,3536 v1(4652,3566)
SWCLK: CN3.2 U1.37 | length 904.3
  Top Layer w6: U1.37 4636.3,3543.7 4652,3528 4726.8,3528 4738,3539.2 4738,3844 4726.6,3855.4 v1(4661.8,3855.4) ; CN3.2 v1(4660,4088.2)
  Bottom Layer w6: v1(4660,4088.2) 4661.8,4086.3 v1(4661.8,3855.4)
SWDIO: CN3.3 U1.34 | length 1175.7
  Top Layer w6: U1.34 4426.9,3445.1 4432,3440 4534,3440 4540,3446 4540,3502 4556,3518 4730.9,3518 4748,3535.1 4748,3874 4739,3883 v1(4694,3883) ; CN3.3 v1(4660,4137.4)
  Bottom Layer w6: v1(4660,4137.4) 4684.6,4137.4 4694,4128 v1(4694,3883)
UART1_RX: CN3.4 U1.43 | length 749.6
  Top Layer w5: U1.43 4563.8,3661.8 4568.8,3666.8 4618.5,3666.8 4634,3682.3 4634,4006 4642,4014 4672,4014 4690,4032 4690,4180 4683.4,4186.6 CN3.4
UART1_TX: CN3.5 U1.42 | length 831.8
  Top Layer w5: U1.42 4560.2,3642.2 4575.8,3657.8 4628,3657.8 4643,3672.8 4643,3997 4650,4004 4676,4004 4702,4030 4702,4228 4694,4236 4599,4236 CN3.5
VCC: C14.2 C15.2 C16.2 C17.2 D1.2 D2.1 D4.1 R10.2 U4.5 U5.5 | length 1891.6
  Top Layer w15: 3674,3702 3712,3702 3723.6,3690.4 R10.2
  Bottom Layer w80: v1(3546,3730) v1(3573.4,3730) v1(3600.9,3730) v1(3628.3,3730) v1(3655.7,3730) v1(3683.2,3757.4) 3683.2,3930.9 3626.6,3987.4 3548.6,3987.4 3492,4044 3492,4420 3576,4504 v1(4179.7,4504) v1(4207.1,4504) v1(4234.6,4504)
  other v1: 3683.2,3730 3546,3757.4 3573.4,3757.4 3600.9,3757.4 3628.3,3757.4 3655.7,3757.4 3908,4479.1 3935.4,4479.1 3908,4506.6 3935.4,4506.6 4179.7,4531.4 4207.1,4531.4 4234.6,4531.4 3908,4534 3935.4,4534
VCC_3V3: C2.2 C3.2 C4.2 C11.2 C12.2 C22.2 C23.2 C24.2 C26.2 R2.2 U1.1 U1.9 U1.24 U1.36 U1.48 U2.5 U6.2 U6.4 U8.3 | length 4428
  Top Layer w15: U8.3 4237.7,3425 C26.2 v1(4292,3409.5) ; U1.24 4225.7,3543.7 4251.1,3569.1 v1(4267.3,3569.1) ; v1(4292,3744) 4308.8,3760.8 U1.9 ; v1(4457.5,3558.6) 4466.3,3549.8 U1.36 ; U1.1 4466.3,3767.1 4459.5,3760.3 U1.48 ; R2.2 v1(4606,3979.8)
  SIG w15: 4290,3482 4292,3480 v1(4292,3409.5) ; 4457.5,3488 v1(4457.5,3558.6) ; v1(4458,3758.9) 4527.1,3758.9 ; 4536,3758 4602,3758 4606,3762 v1(4606,3979.8)
  SIG w20: v1(4174,3944.7) v1(4174,3878) 4210,3842 4274,3842 4296,3820 4296,3748 v1(4292,3744) 4293.3,3742.7 4293.3,3613.5 4292,3612.2 4292,3593.8 v1(4267.3,3569.1) 4267.3,3488.6 4266.7,3488
  SIG w45: v1(3185,4395.3) 3185,3519 3216,3488 4266.7,3488 4457.5,3488 4506,3488 4536,3518 4536,3758
  Bottom Layer w15: U6.4 4073,3837 4113.3,3877.3 C24.2 ; U6.2 4127.1,3937 C23.2 ; v1(4174,3878) 4173.3,3877.3 C24.2 ; v1(4174,3944.7) C23.2 ; C24.2 C23.2
VCC_IN: D1.1 U7.2
VREF_A: C19.2 R7.2 U4.4 | length 319.9
  Top Layer w10: R7.2 C19.2 3806.3,4159.7 3818,4148 3884,4148 3894,4158 3894,4216 3875.2,4234.8 U4.4
VREF_B: C21.2 R9.2 U5.4 | length 154.9
  Top Layer w10: R9.2 C21.2 4165.4,4222.6 4150.8,4237.2 U5.4
pads on no net: U1.2 U1.3 U1.4 U1.11 U1.16 U1.17 U1.18 U1.19 U1.26 U1.27 U1.28 U1.29 U1.30 U1.31 U6.3 U8.5 U8.8

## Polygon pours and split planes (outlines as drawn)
GND on Top Layer (solid, remove dead copper, pour order 0): 3010,4798 3010,3036 4816,3036 4816,4798
GND on SIG (solid, remove dead copper): 3000,4816 3000,3032 4812,3032 4812,4816
GND on Bottom Layer (solid, remove dead copper, pour order 2): 3000,4820 3000,3036 4812,3036 4812,4820

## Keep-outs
Top Layer:
  region: 4390,3788 4362.3,3788 4360,3790.3 4360,3854 4354,3860 4342,3860 4318,3884 4318,3938 4316,3940 4258,3940 4254,3944 4254,4130 4262,4138 4496,4138 4502,4132 4502,3948 4498,3944 4452,3944 4440,3932 4440,3884 4416,3860 4396,3860 4394,3858 4394,3792
Board Outline Layer:
  region: 3866.2,4008.5 3866.2,3815.5 4019.8,3815.5 4019.8,4008.5
  region: 3391.6,3871.1 3391.6,3800.3 3427.8,3800.3 3427.8,3871.1
  lines w3.9: 3111.2,3282.1 3308.1,3085.2 4567.9,3085.2 4764.8,3282.1 4764.8,4541.9 4567.9,4738.8 3308.1,4738.8 3111.2,4541.9 3111.2,3282.1

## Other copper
Top Layer:
  region net OUT_A-: 3732,4714 3816,4714 3830,4700 3830,4618 3814,4602 3764,4602 3746,4584 3746,4466 3738,4458 3716,4458 3710,4464 3710,4692
  region net OUT_A+: 3850,4714 3914,4714 3926,4702 3926,4602 3906,4582 3874,4582 3846,4554 3846,4466 3838,4458 3814,4458 3806,4466 3806,4568 3842,4604 3842,4706
  region net OUT_B-: 3952,4714 4010,4714 4024,4700 4024,4606 4018,4600 4018,4464 4012,4458 3984,4458 3976,4466 3976,4558 3946,4588 3946,4708
  region net OUT_B+: 4054,4714 4116,4714 4130,4700 4130,4606 4122,4598 4122,4466 4114,4458 4086,4458 4078,4466 4078,4596 4072,4602 4050,4602 4044,4608 4044,4704
  region net VCC: 3862,4546 3944,4546 3952,4538 3952,4436 3942,4426 3902,4426 3892,4436 3892,4452 3888,4456 3862,4456 3856,4462 3856,4540
  region net VCC: 4138,4546 4254,4546 4258,4542 4258,4496 4252,4490 4196,4490 4190,4484 4190,4466 4182,4458 4142,4458 4130,4470 4130,4538
  region net VCC_IN: 3749.6,3098 3446,3098 3432,3112 3432,3218 3444,3230 3734,3230 3758,3206 3758,3106.4
  region net VCC: 3550,3778 3694,3778 3698,3774 3698,3690 3690,3682 3584,3682 3574,3672 3574,3478 3596,3456 3718,3456 3730,3444 3730,3278 3700.6,3248.6 3449.4,3248.6 3440,3258 3440,3378 3434,3384 3384,3384 3376,3392 3376,3649.9 3388.1,3662 3428,3662 3438.1,3672.1 3438.1,3717.1 3444.8,3723.7 3531.7,3723.7 3536,3728 3536,3764
  region net $1N216: 3977,4426 ccw(c3977,4421) 3972,4421 3972,4352.9 ccw(c3977,4352.9) 3977,4347.9 3990.8,4347.9 ccw(c3990.8,4352.9) 3995.8,4352.9 3995.8,4421 ccw(c3990.8,4421) 3990.8,4426
  region net $1N216: 4169.7,4428.6 ccw(c4169.7,4423.6) 4164.7,4423.6 4164.7,4355.5 ccw(c4169.7,4355.5) 4169.7,4350.5 4183.5,4350.5 ccw(c4183.5,4355.5) 4188.5,4355.5 4188.5,4423.6 ccw(c4183.5,4423.6) 4183.5,4428.6
  region net $1N216: 4305,4472.2 ccw(c4305,4467.2) 4300,4467.2 4300,4421.2 ccw(c4305,4421.2) 4305,4416.2 4331,4416.2 ccw(c4331,4421.2) 4336,4421.2 4336,4467.2 ccw(c4331,4467.2) 4331,4472.2
  region net $1N214: 3876.4,4418.7 ccw(c3876.4,4413.7) 3871.4,4413.7 3871.4,4345.5 ccw(c3876.4,4345.5) 3876.4,4340.5 3890.2,4340.5 ccw(c3890.2,4345.5) 3895.2,4345.5 3895.2,4413.7 ccw(c3890.2,4413.7) 3890.2,4418.7
  region net $1N214: 3693,4423.4 ccw(c3693,4418.4) 3688,4418.4 3688,4350.3 ccw(c3693,4350.3) 3693,4345.3 3706.7,4345.3 ccw(c3706.7,4350.3) 3711.7,4350.3 3711.7,4418.4 ccw(c3706.7,4418.4) 3706.7,4423.4
  region net $1N214: 3592,4561 ccw(c3597,4561) 3597,4556 3643,4556 ccw(c3643,4561) 3648,4561 3648,4587 ccw(c3643,4587) 3643,4592 3597,4592 ccw(c3597,4587) 3592,4587
  region net $1N90: 3268,3862 3293.6,3862 3297.4,3858.2 3297.4,3780.6 3342,3736 3398,3736 3416,3718 3416,3678 3408,3670 3312,3670 3301.6,3680.4 3301.6,3726.6 3294.2,3734 3156,3734 3152,3738 3152,3782 3158,3788 3256,3788 3266,3798 3266,3860
  region net $1N67: 3306,3862 3322,3862 3326,3866 3326,3880 3338,3892 3408,3892 3412.4,3896.4 3412.4,4000.4 3420,4008 3462,4008 3466,4004 3466,3892 3448,3874 3394,3874 3392,3872 3392,3796 3396,3792 3402,3792 3411.9,3782.1 3411.9,3757.9 3406,3752 3364,3752 3334,3782 3316,3782 3304,3794 3304,3860
  region net +5V: 3430,3864 3478,3864 3484,3870 3484,4002 3490,4008 3536,4008 3543.4,4000.6 3543.4,3809.4 3536,3802 3434,3802 3428,3808 3428,3862
  region net +5V: 3306,4208 3314,4216 3420,4216 3424,4212 3424,4124 3416,4116 3388,4116 3382,4122 3382,4190 3376,4196 3350,4196 3344,4190 3344,4126 3336,4118 3310,4118 3306,4122
  region net $1N70: 3352,4006 3400,4006 3404,4002 3404,3902 3400,3898 3358,3898 3352,3904 3306,3904 3304,3906 3304,3962 3306,3964 3344,3964 3350,3970 3350,4004
  region net VCC_3V3: 3191.1,4217 3191.1,4217.2 3160.8,4217.2 3150,4228 3150,4394 3162,4406 3210,4406 3218,4398 3218,4296 3222,4292 3342,4292 3350,4284 3350,4238 3340,4228 3302,4228 3291,4217
Bottom Layer:
  region net $1N216: 4043,4598 ccw(c4043,4593) 4038,4593 4038,4555 ccw(c4043,4555) 4043,4550 4069,4550 ccw(c4069,4555) 4074,4555 4074,4593 ccw(c4069,4593) 4069,4598
  region net $1N214: 3767.4,4598 ccw(c3767.4,4593) 3762.4,4593 3762.4,4555 ccw(c3767.4,4555) 3767.4,4550 3793.4,4550 ccw(c3793.4,4555) 3798.4,4555 3798.4,4593 ccw(c3793.4,4593) 3793.4,4598

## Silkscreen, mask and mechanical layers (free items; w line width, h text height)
Top Silkscreen Layer:
  text "GND / TX / RX / DIO / CLK / GND" at 4478,4170 h30
  text "l" at 4264,3154 h80
  text "H" at 3946,3148 h80
  text "24V" at 3316,3098 h80
  text "-" at 3904,3080 h80
  text "+" at 3594,3072 h80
